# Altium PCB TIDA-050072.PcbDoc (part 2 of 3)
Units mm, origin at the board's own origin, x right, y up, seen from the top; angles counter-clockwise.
Board outline 125.73 x 87.63 mm, 2 copper layers (Top Layer, Bottom Layer), stack 1.575 mm thick; 105 components, 63 nets, 347 pads, 390 vias.
Unrouted connection lines stored in the file: 6.
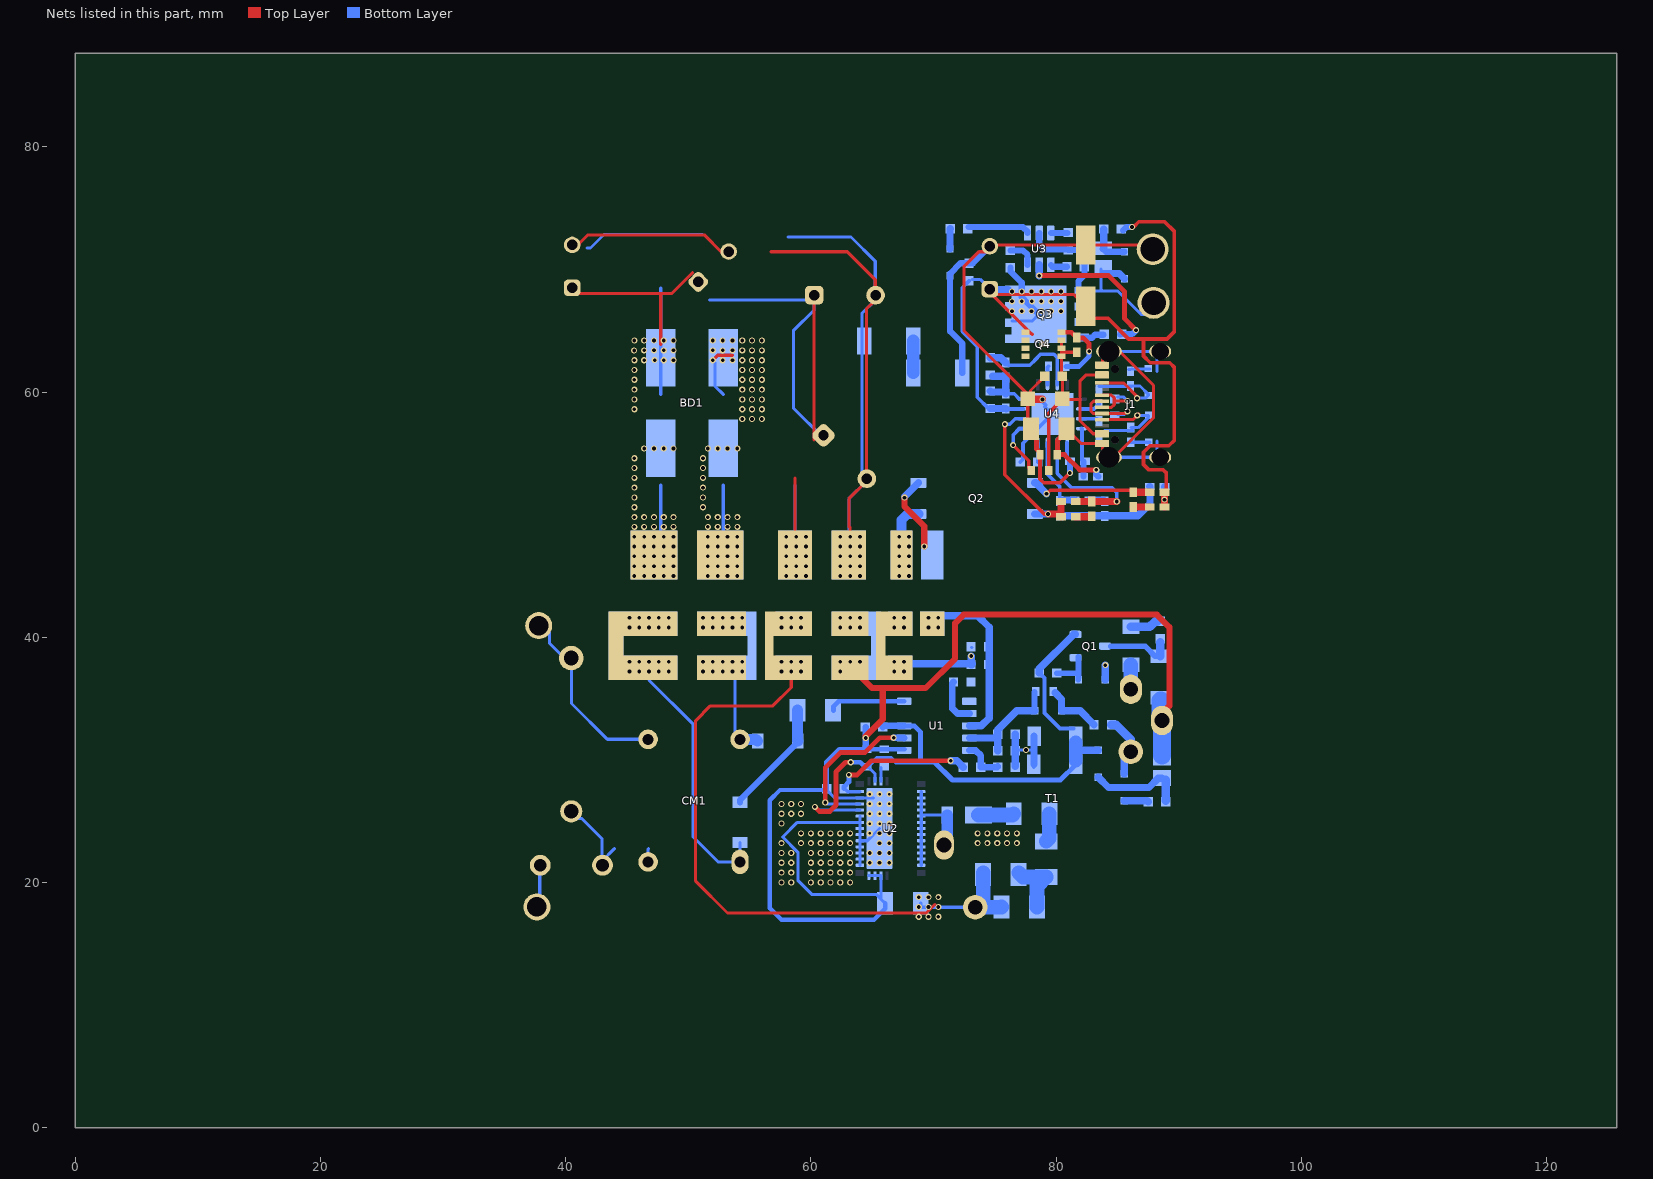
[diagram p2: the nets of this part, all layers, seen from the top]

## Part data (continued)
R8 R9: library part CMP-0018730-2, "RES, 7.5, 5%, 0.25 W, 1206", Manufacturer=Vishay-Dale, Power_W=250mW, Supplier Part Number 1=541-7.5ECT-ND, TempCo="200 ppm/C", Tolerance_%=5%, Value2=0.25W, Value_Code=7R50, ValueDisplayed=7.5
R10 R12: library part CMP-0022892-5, "RES, 1.80 k, 1%, 0.1 W, 0603", Manufacturer=Yageo, Power_W=100mW, Supplier Part Number 1=311-1.80KHRCT-ND, TempCo="100 ppm/C", Tolerance_%=1%, Value2=0.1W, Value_Code=1k80, ValueDisplayed=1.80k
R11: library part CMP-0023032-4, "RES, 330 k, 1%, 0.1 W, 0603", Manufacturer=Yageo, Power_W=100mW, Supplier Part Number 1=311-330KHRCT-ND, TempCo="100 ppm/C", Tolerance_%=1%, Value2=0.1W, Value_Code=330k
R13 R16 R18: library part CMP-0025821-1, "RES, 4.7, 5%, 0.1 W, 0603", Manufacturer=Vishay-Dale, Power_W=100mW, Supplier Part Number 1=541-4.7GCT-ND, TempCo="200 ppm/C", Tolerance_%=5%, Value2=0.1W, Value_Code=4R70, ValueDisplayed=4.7
R14: library part CMP-0023073-5, "RES, 39.0 k, 1%, 0.1 W, 0603", Manufacturer=Yageo, Power_W=100mW, Supplier Part Number 1=311-39.0KHRCT-ND, TempCo="100 ppm/C", Tolerance_%=1%, Value2=0.1W, Value_Code=39k0, ValueDisplayed=39.0k
R15: library part CMP-0025812-1, "RES, 470 k, 5%, 0.1 W, 0603", Manufacturer=Vishay-Dale, Power_W=100mW, Supplier Part Number 1=541-470KGCT-ND, TempCo="200 ppm/C", Tolerance_%=5%, Value2=0.1W, Value_Code=470k
R17: library part CMP-0020631-1, "RES, 12, 5%, 0.125 W, 0805", Manufacturer=Panasonic, Power_W=125mW, Supplier Part Number 1=P12ACT-ND, TempCo="200 ppm/C", Tolerance_%=5%, Value2=0.125W, Value_Code=12R0, ValueDisplayed=12
R19 R21: library part CMP-0025910-5, "RES, 300, 5%, 0.1 W, 0603", Manufacturer=Yageo, Power_W=100mW, Supplier Part Number 1=311-300GRCT-ND, TempCo="100 ppm/C", Tolerance_%=5%, Value2=0.1W, Value_Code=300R, ValueDisplayed=300
R22: library part CMP-0025975-2, "RES, 11.0 k, 1%, 0.063 W, 0402", Manufacturer=Vishay-Dale, Power_W=63mW, Supplier Part Number 1=541-11.0KLCT-ND, TempCo="100 ppm/C", Tolerance_%=1%, Value2=0.063W, Value_Code=11k0, ValueDisplayed=11.0k
R23: library part CMP-0026402-1, "RES, 499, 1%, 0.063 W, 0402", Manufacturer=Vishay-Dale, Power_W=63mW, Supplier Part Number 1=541-499LCT-ND, TempCo="100 ppm/C", Tolerance_%=1%, Value2=0.063W, Value_Code=499R, ValueDisplayed=499
R24 R25: library part CMP-0027003-2, "RES, 47, 5%, 0.063 W, 0402", Manufacturer=Rohm, Power_W=63mW, Supplier Part Number 1=RHM47JCT-ND, TempCo="200 ppm/C", Tolerance_%=5%, Value2=0.063W, Value_Code=47R0, ValueDisplayed=47
R26: library part CMP-0026907-1, "RES, 33 k, 5%, 0.063 W, 0402", Manufacturer=Vishay-Dale, Power_W=63mW, Supplier Part Number 1=541-33KJCT-ND, TempCo="200 ppm/C", Tolerance_%=5%, Value2=0.063W, Value_Code=33k0, ValueDisplayed=33k
R27: library part CMP-0025886-5, "RES, 10 k, 5%, 0.1 W, 0603", Manufacturer=Yageo, Power_W=100mW, Supplier Part Number 1=311-10KGRCT-ND, TempCo="100 ppm/C", Tolerance_%=5%, Value2=0.1W, Value_Code=10k0, ValueDisplayed=10k
R28: library part CMP-0026859-2, "RES, 1.0 M, 5%, 0.063 W, AEC-Q200 Grade 0, 0402", Manufacturer=Vishay-Dale, Power_W=63mW, Supplier Part Number 1=541-1.0MJCT-ND, TempCo="200 ppm/C", Tolerance_%=5%, Value2=0.063W, Value_Code=1M00, ValueDisplayed=1.0M
R29: library part CMP-0022109-1, "RES, 1.00 k, 1%, 0.1 W, 0603", Manufacturer=Vishay-Dale, Power_W=100mW, Supplier Part Number 1=541-1.00KHCT-ND, TempCo="100 ppm/C", Tolerance_%=1%, Value2=0.1W, Value_Code=1k00, ValueDisplayed=1.00k
R30: library part CMP-0078497-1, "RES, 0.005, 1%, 1 W, 1206", Manufacturer=Riedon, Power_W=1W, Supplier Part Number 1=696-1372-1-ND, TempCo="50 ppm/C", Tolerance_%=1%, Value_Code=5L000, ValueDisplayed=0.005
R31: library part CMP-0026951-3, "RES, 5.1 k, 5%, 0.063 W, 0402", Manufacturer=Vishay-Dale, Power_W=63mW, Supplier Part Number 1=541-5.1KJCT-ND, TempCo="200 ppm/C", Tolerance_%=5%, Value2=0.063W, Value_Code=5k10, ValueDisplayed=5.1k
R32: library part CMP-0026938-5, "RES, 4.7 k, 5%, 0.063 W, AEC-Q200 Grade 0, 0402", Manufacturer=Vishay-Dale, Power_W=63mW, Supplier Part Number 1=541-4.7KJCT-ND, TempCo="200 ppm/C", Tolerance_%=5%, Value2=0.063W, Value_Code=4k70, ValueDisplayed=4.7k
R33: library part CMP-0026935-2, "RES, 47 k, 5%, 0.063 W, 0402", Manufacturer=Vishay-Dale, Power_W=63mW, Supplier Part Number 1=541-47KJCT-ND, TempCo="200 ppm/C", Tolerance_%=5%, Value2=0.063W, Value_Code=47k0, ValueDisplayed=47k
R34: library part CMP-0025700-3, "RES, 100, 5%, 0.1 W, 0603", Manufacturer=Vishay-Dale, Power_W=100mW, Supplier Part Number 1=541-100GCT-ND, TempCo="200 ppm/C", Tolerance_%=5%, Value2=0.1W, Value_Code=100R, ValueDisplayed=100
RT1: library part CMP-0002440-2, "Thermistor NTC, 220k ohm, 3%, 0603", Manufacturer=MuRata, Power_W=100mW, Supplier Part Number 1=490-8456-1-ND, Tolerance_%=3%
T1: library part RM8_65W, Alternate Manufacturer=-, Manufacturer="Used in BOM report"
U1: library part CMP-0094882-1, "Converter Offline Flyback Topology 50kHz", Manufacturer=onsemi, Max Power Dissipation=330mW, Max Supply Voltage=28V, Min Supply Voltage=8.5V, Mouser Part Number=863-CP1342AMDCDD1R2G, Nominal Supply Current=0.115-1mA, Operating Temperature Range="-40°C to +125°C", Supplier Part Number 1=NCP1342AMAACD1R2GOSCT-ND, Switching Frequency=25kHz
U2: library part CMP-0096535-2, "650-V GaN FET With Integrated Driver and Current Sense Emulation", Manufacturer="Texas Instruments", Max Supply Voltage=26V, Min Supply Voltage=10V, Operating Temperature Range="-40°C to +175°C"
U3: library part CMP-0086802-1, "FAST TURN-OFF INTELLIGENT RECTIF", Manufacturer="Monolithic Power Systems"
U4: library part CMP-0087009-1, "USB PD/QC4/QC4+ Controller", Manufacturer=Weltrend

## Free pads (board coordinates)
  rect 1.2x5.6 smd: 1(44.1,39.3)
  rect 1.2x5.6 smd far side: 1(44.1,39.3)
  rect 4.6x2 smd: 1(46.8,37.5) 1(46.8,41.1)
  rect 4.6x2 smd far side: 1(46.8,37.5) 1(46.8,41.1)
  rect 3.8x4 smd: 1(47.2,46.7) 1(52.6,46.7)
  rect 3.8x4 smd far side: 1(47.2,46.7) 1(52.6,46.7)
  rect 4x2 smd: 1(52.7,37.5) 1(52.7,41.1)
  rect 4.4x2 smd far side: 1(52.9,37.5) 1(52.9,41.1)
  rect 0.7x5.6 smd far side: 1(55.2,39.3)
  rect 0.7x5.6 smd: 1(56.6,39.3)
  rect 3.4x2 smd: 1(58.4,37.5) 1(58.4,41.1)
  rect 3x2 smd far side: 1(58.6,37.5) 1(58.6,41.1)
  rect 2.8x4 smd: 1(58.7,46.7) 1(63.1,46.7)
  rect 2.8x4 smd far side: 1(58.7,46.7) 1(63.1,46.7)
  rect 3x2 smd: 1(63.2,37.5) 1(63.2,41.1)
  rect 3.4x2 smd far side: 1(63.4,37.5) 1(63.4,41.1)
  rect 0.8x5.6 smd far side: 1(65.3,39.3)
  rect 0.8x5.6 smd: 1(65.7,39.3)
  rect 2.4x2 smd: 1(67.1,37.5) 1(67.1,41.1)
  rect 2x2 smd far side: 1(67.3,37.5) 1(67.3,41.1) 1(69.9,41.1)
  rect 1.8x4 smd: 1(67.4,46.7)
  rect 1.8x4 smd far side: 1(67.4,46.7) 1(69.9,46.7)
  rect 2x2 smd: 1(69.9,41.1)

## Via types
v1: diameter 0.5, hole 0.3, Top Layer to Bottom Layer, 375 vias
v2: diameter 0.5, hole 0.2, Top Layer to Bottom Layer, tented both sides, 13 vias
v3: diameter 0.5, hole 0.3, Top Layer to Bottom Layer, tented both sides, 2 vias

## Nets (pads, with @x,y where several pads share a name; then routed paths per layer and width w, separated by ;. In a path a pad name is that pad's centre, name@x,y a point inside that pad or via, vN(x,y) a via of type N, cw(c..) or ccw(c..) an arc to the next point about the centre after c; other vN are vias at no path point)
AUX_QR: D6.2 R12.2 T1.4 | length 5.1
  Bottom Layer w0.6: D6.2@85.575,28.85 85.575,30.145 T1.4@86.1,30.67
  Bottom Layer w0.7: R12.2@84.518,32.868 84.896,32.868 86.1,31.664 T1.4@86.1,30.67
CC1: C33.1 D13.2 J1.A5 R25.1 | length 9
  Top Layer w0.254: J1.A5@83.791,57.75 86.275,57.75 v1@86.75,58.225
  Bottom Layer w0.254: R25.1@83.5,56.45 83.561,56.45 83.966,56.855 C33.1@86.255,56.855 ; C33.1@86.1,57.1 86.7,57.1 87.55,57.95 D13.2@87.55,58.1 v1(86.625,58.1)
CC2: C34.1 D14.2 J1.B5 R24.1 | length 8.9
  Top Layer w0.254: J1.B5@83.791,60.75 85.5,60.75 v1@86.75,59.5
  Bottom Layer w0.254: R24.1@83.525,60.475 C34.1@86.15,60.475 ; C34.1@86.075,60.5 86.85,60.5 87.525,59.825 D14.2@87.525,59.725 87.3,59.5 v1(86.6,59.5)
CS_QR: R3.1 R6.1 U2.33 | length 12.7
  Top Layer w0.4: v1(63.1,28.775) 63.777,28.775 64.927,29.925 v1(71.4,29.925)
  Bottom Layer w0.254: R3.1@62.711,27.7 62.736,27.675 63.011,27.4 U2.33@64,27.4
  Bottom Layer w0.4: R3.1@62.711,27.65 62.711,27.7 62.711,27.811 63.1,28.2 v1(63.1,28.775)
  Bottom Layer w0.6: v1(71.4,29.925) 71.914,29.925 R6.1@72.439,29.4
DRV_QR: U1.7 U2.31 | length 13.2
  Top Layer w0.4: v1(61.175,26.525) 61.175,29.359 62.4,30.584 64.404,30.584 65.62,31.8 v1(66.75,31.8)
  Bottom Layer w0.254: v1(61.175,26.525) 61.3,26.4 U2.31@64,26.4
  Bottom Layer w0.5: v1(66.75,31.8) 67.59,31.8 U1.7@67.615,31.775 U1.7@67.597,31.757
FLT_QR: U1.1
G: BD1.4 C2.2 C3.2 C4.2 C5.2 C6.2 C6A.2 C7.2 C8.2 C10.2 C11.2 C12.2 C13.2 C14.2 C15.2 CY1.2 D5.2 pad.1@63.1,46.7 pad.1@63.2,37.5 pad.1@63.2,41.1 pad.1@63.4,37.5 pad.1@63.4,41.1 pad.1@65.3,39.3 pad.1@65.7,39.3 pad.1@67.1,37.5 pad.1@67.1,41.1 pad.1@67.3,37.5 pad.1@67.3,41.1 pad.1@67.4,46.7 Q2.4 R3.2 R4.2 R5.2 R10.1 R14.1 T1.6 U1.6 U2.17 U2.18 U2.19 U2.21 U2.22 U2.23 U2.24 U2.25 U2.26 U2.27 U2.28 U2.29 U2.32 U2.39 | length 238.1
  Top Layer w0.254: C6.2@40.525,71.525 41.825,72.825 51.3,72.825 C6A.2@52.75,71.375 ; v1(52,62.6) 52.4,63 53.6,63 ; 56.75,71.45 62.975,71.45 65.25,69.175 65.25,67.5 64.543,66.793 64.543,52.732 63.1,51.289 63.1,49 ; v1(62.4,41.6) 62.9,41.1 pad.1@63.2,41.1 ; v1(62.4,46.6) 62.729,46.6 pad.1@62.8,46.529 ; pad.1@63.1,47.4 62.8,47.1 62.8,46.6 63,46.6 63.071,46.671 pad.1@63.428,46.671 ; pad.1@63.2,37.5 63.2,37.6 63.265,37.665 pad.1@63.6,38 ; v1(63.2,47.4) v1(63.2,48.2) 63.2,49 ; pad.1@67.2,45.4 67.4,45.6 pad.1@67.4,46.7 ; T1.6@88.64,33.21 T1.6@88.64,33.79
  Top Layer w0.5: pad.1@63.2,37.5 63.344,37.5 64.994,35.85 65.861,35.85 ; v1(64.475,31.775) 64.475,31.925 65.861,33.311 65.861,35.85 ; T1.6@88.64,33.79 89.25,34.4 89.25,40.827 88.227,41.85 72.475,41.85 71.763,41.138 71.763,38.263 69.35,35.85 65.861,35.85
  Bottom Layer w0.254: 41.75,71.75 42.028,71.75 43.128,72.85 51.168,72.85 ; 52.85,59.81 52.175,60.485 52.175,62.425 v1(52,62.6) 52.4,63 BD1.4@53.6,63 ; 58.125,72.65 63.275,72.65 65.25,70.675 65.25,67.5 64.175,66.425 64.175,53.1 64.543,52.732 63.1,51.289 63.1,47.4 62.8,47.1 62.8,46.6 63,46.6 63.071,46.671 pad.1@63.428,46.671 ; R3.2@61.289,27.536 61.925,26.9 U2.32@64,26.9 U2.39@65.1,26.9 ; v1(62.4,41.6) 62.9,41.1 pad.1@63.4,41.1 ; v1(62.4,46.6) 62.729,46.6 pad.1@62.8,46.529 ; U2.21@64,21.4 U2.22@64,21.9 U2.23@64,22.4 U2.24@64,22.9 U2.25@64,23.4 ; U2.29@64,25.4 U2.28@64,24.9 ; U2.19@64.725,20.55 U2.18@65.225,20.55 U2.17@65.725,20.55 C8.2@65.725,18.636 ; U2.39@65.6,24.4 64.6,23.4 U2.25@64,23.4 ; C8.2@66.061,18.3 C8.2@65.725,18.636 ; pad.1@67.2,45.4 67.4,45.6 pad.1@67.4,46.7 ; C15.2@73.114,39.162 C15.2@73.128,39.176 ; R10.1@76.674,30.75 76.724,30.8 v1(77.55,30.8) 78.154,30.8 78.204,30.85 ; C13.2@78.177,29.375 C13.2@78.225,29.423 ; U2.25@64,23.4 U2.26@64,23.9 U2.27@64,24.4 U2.28@64,24.9 ; U2.28@64,24.9 58.9,24.9 57.7,23.7 58.937,22.463 58.937,20.162 60.1,19 65.361,19 C8.2@65.725,18.636
  Bottom Layer w0.35: R3.2@61.289,27.536 57.486,27.536 56.65,26.7 56.65,17.9 57.6,16.95 65.15,16.95 66.061,17.861 C8.2@66.061,18.3
  Bottom Layer w0.4: R3.2@61.289,27.536 R3.2@61.289,27.65 61.289,29.839 62.311,30.861 C3.2@64.575,30.861 ; C3.2@64.7,30.861 R4.2@65.975,30.861 U1.6@67.64,30.861
  Bottom Layer w0.5: C3.2@64.475,31 v1(64.475,31.775) C2.2@64.475,32.678
  Bottom Layer w0.6: pad.1@67.6,37.4 68.05,37.85 R14.1@73.15,37.85 ; R14.1@73.075,37.761 R14.1@73.075,37.975 ; R14.1@73.075,38 v1(73.075,38.475) ; R14.1@73.114,37.75 R14.1@73.125,37.761 ; C7.2@76.674,29.45 R10.1@76.674,30.75 C10.2@76.674,32.09 ; C13.2@78.2,29.65 78.204,29.654 78.204,30.85 C14.2@78.204,31.914 ; D5.2@84.025,36.525 v1(84.025,37.725)
  Bottom Layer w0.8: pad.1@67.4,46.7 67.4,49.575 67.875,50.05 Q2.4@68.775,50.05
  Bottom Layer w1.5: T1.6@88.536,33.104 C12.2@88.536,34.819 ; C11.2@88.64,30.386 T1.6@88.64,33.396
  other v1: 57.6,20 58.4,20 60,20 60.8,20 61.6,20 62.4,20 63.2,20 57.6,20.8 58.4,20.8 60,20.8 60.8,20.8 61.6,20.8 62.4,20.8 63.2,20.8 57.6,21.6 58.4,21.6 60,21.6 60.8,21.6 61.6,21.6 62.4,21.6 63.2,21.6 64.8,21.6 65.6,21.6 66.4,21.6 57.6,22.4 58.4,22.4 60,22.4 60.8,22.4 61.6,22.4 62.4,22.4 63.2,22.4 64.8,22.4 65.6,22.4 66.4,22.4 57.6,23.2 59.2,23.2 60,23.2 60.8,23.2 61.6,23.2 62.4,23.2 63.2,23.2 65.6,23.2 66.4,23.2 59.2,24 60,24 60.8,24 61.6,24 62.4,24 63.2,24 57.6,24.8 57.6,25.6 58.4,25.6 59.2,25.6 57.6,26.4 58.4,26.4 59.2,26.4 62.4,37.2 66.8,37.2 67.6,37.2 62.4,38 63.2,38 64,38 66.8,38 67.6,38 62.4,40.8 63.2,40.8 64,40.8 66.8,40.8 67.6,40.8 63.2,41.6 64,41.6 66.8,41.6 67.6,41.6 62.4,45 63.2,45 64,45 67.2,45 68,45 62.4,45.8 63.2,45.8 64,45.8 67.2,45.8 68,45.8 63.2,46.6 64,46.6 67.2,46.6 68,46.6 62.4,47.4 64,47.4 67.2,47.4 68,47.4 62.4,48.2 64,48.2 67.2,48.2 68,48.2 54.4,57.8 55.2,57.8 56,57.8 54.4,58.6 55.2,58.6 56,58.6 54.4,59.4 55.2,59.4 56,59.4 54.4,60.2 55.2,60.2 56,60.2 54.4,61 55.2,61 56,61 54.4,61.8 55.2,61.8 56,61.8 52.8,62.6 53.6,62.6 54.4,62.6 55.2,62.6 56,62.6 52,63.4 52.8,63.4 53.6,63.4 54.4,63.4 55.2,63.4 56,63.4 52,64.2 52.8,64.2 53.6,64.2 54.4,64.2 55.2,64.2 56,64.2
  other v2: 64.8,24 64.8,24.8 65.6,24.8 66.4,24.8 64.8,25.6 65.6,25.6 66.4,25.6 64.8,26.4 65.6,26.4 66.4,26.4 64.8,27.2 65.6,27.2 66.4,27.2
  other v3: 65.6,24 66.4,24
GPD: R27.1 U4.2 | length 1.5
  Bottom Layer w0.3: U4.2@79.3,60.6 79.3,62.011 R27.1@79.389,62.1
Net+_1: +.1 C17.2 D10.2 Q3.1 Q3.2 Q3.3 R17.1 R20.1 U3.2 | length 20.6
  Bottom Layer w0.254: Q3.3@82.1,65.705 Q3.2@82.1,66.975 Q3.1@82.1,68.245 83.674,68.245 83.8,68.245 ; R17.1@83.674,70.017 83.674,69.675 83.674,68.371 83.8,68.245 ; +.1@87.8,66.35 86.925,66.35 85.03,68.245 83.8,68.245
  Bottom Layer w0.5: U3.2@78.625,72.975 78.625,72.05 79.025,71.65 R20.1@80.85,71.65 ; R20.1@81,71.589 81.739,71.589 82.311,71.017 C17.2@82.311,70.225 82.311,69.526 81.825,69.04 Q3.1@81.825,68.273
  Bottom Layer w0.6: 83.864,69.675 85.164,69.675 D10.2@85.589,69.25
NetBD1_1: BD1.1 C4.1 C5.1 C6.1 C6A.1 C8.1 C9.1 pad.1@56.6,39.3 pad.1@58.4,37.5 pad.1@58.4,41.1 pad.1@58.6,37.5 pad.1@58.6,41.1 pad.1@58.7,46.7 R7.2 T1.1 | length 132.6
  Top Layer w0.254: C6.1@40.525,68.025 47.7,68.025 ; 47.75,63.9 47.75,67.975 47.7,68.025 ; 50.35,69.75 48.625,68.025 47.7,68.025 ; pad.1@57.4,41.664 57.964,41.1 pad.1@58.4,41.1 ; 58.7,52.975 58.7,48.2 58.7,47.4 pad.1@58.7,46.7 v1(58.8,46.6) ; pad.1@58.8,37.6 58.5,37.6 pad.1@58.4,37.5 58.4,35.9 56.9,34.4 51.8,34.4 50.6,33.2 50.6,20.1 53.2,17.5 69.414,17.5 70.114,18.2 ; v1(58.8,45.8) v1(58.8,46.6) ; v1(59.6,45) v1(59.6,45.8) v1(58.8,46.6) ; C4.1@60.25,67.5 60.25,56.1 60.418,56.268 C5.1@61.007,56.268
  Bottom Layer w0.254: 47.75,59.81 47.75,63.9 47.75,68.5 ; 51.75,67.5 60.25,67.5 60.25,66.675 58.575,65 58.575,58.7 C5.1@61.007,56.268 ; pad.1@57.4,41.664 57.964,41.1 pad.1@58.6,41.1 ; pad.1@58.6,37.5 58.7,37.6 pad.1@58.8,37.6 ; 58.7,52.4 58.7,48.2 58.7,47.4 pad.1@58.7,46.7 v1(58.8,46.6) ; v1(58.8,45.8) v1(58.8,46.6) ; v1(59.6,45) v1(59.6,45.8) v1(58.8,46.6) ; C8.1@68.961,18.3 68.961,18.089 69.08,17.97 T1.1@73.4,17.97
  Bottom Layer w1.2: C9.1@74.05,20.8 74.05,18.62 T1.1@73.4,17.97 75.52,17.97 R7.2@75.55,18
  other v1: 68.8,17.2 69.6,17.2 70.4,17.2 68.8,18 69.6,18 70.4,18 68.8,18.8 69.6,18.8 70.4,18.8 57.6,37.2 58.4,37.2 59.2,37.2 57.6,38 58.4,38 59.2,38 57.6,40.8 58.4,40.8 59.2,40.8 57.6,41.6 58.4,41.6 59.2,41.6 58,45 58.8,45 58,45.8 58,46.6 59.6,46.6 58,47.4 58.8,47.4 59.6,47.4 58,48.2 58.8,48.2 59.6,48.2 45.6,58.6 45.6,59.4 45.6,60.2 45.6,61 45.6,61.8 45.6,62.6 46.4,62.6 47.257,62.602 48,62.6 48.8,62.6 45.581,63.387 46.4,63.4 47.2,63.4 48,63.4 48.8,63.4 45.6,64.2 46.4,64.2 47.2,64.2 48,64.2 48.8,64.2
NetBD1_2: BD1.2 CM1.4 D2.2 pad.1@44.1,39.3 pad.1@46.8,37.5 pad.1@46.8,41.1 pad.1@47.2,46.7 | length 34.5
  Top Layer w0.254: v1(48.4,40.8) 48.1,41.1 pad.1@46.8,41.1 47.3,41.6 v1(48.4,41.6)
  Bottom Layer w0.254: pad.1@46.8,37.5 46.8,36.5 50.4,32.9 50.4,23.7 52.425,21.675 CM1.4@54.225,21.675 D2.2@54.225,23.262 ; pad.1@47.2,46.7 47.75,47.25 47.75,52.41 ; v1(48.4,40.8) 48.1,41.1 pad.1@46.8,41.1 47.3,41.6 v1(48.4,41.6)
  other v1: 45.2,37.2 46,37.2 46.8,37.2 47.6,37.2 48.4,37.2 45.2,38 46,38 46.8,38 47.6,38 48.4,38 45.2,40.8 46,40.8 46.8,40.8 47.6,40.8 45.2,41.6 46,41.6 46.8,41.6 47.6,41.6 45.6,45 46.4,45 47.2,45 48,45 48.8,45 45.6,45.8 46.4,45.8 47.2,45.8 48,45.8 48.8,45.8 45.6,46.6 46.4,46.6 47.2,46.6 48,46.6 48.8,46.6 45.6,47.4 46.4,47.4 47.187,47.4 48.01,47.4 48.8,47.4 45.6,48.2 46.4,48.2 47.2,48.2 48,48.2 48.8,48.2 45.6,49 46.4,49 47.2,49 48,49 48.8,49 45.6,49.8 46.4,49.8 47.2,49.8 48,49.8 48.8,49.8 45.6,50.6 45.6,51.4 45.6,52.2 45.6,53 45.6,53.8 45.6,54.6 46.4,55.4 47.2,55.4 48,55.4 48.8,55.4
NetBD1_3: BD1.3 CM1.3 D1.2 pad.1@52.6,46.7 pad.1@52.7,37.5 pad.1@52.7,41.1 pad.1@52.9,37.5 pad.1@52.9,41.1 pad.1@55.2,39.3 | length 30.1
  Top Layer w0.254: pad.1@51.2,48.2 51.2,48.1 pad.1@51.95,47.35 ; pad.1@52,47.4 52,47.3 52.12,47.18 pad.1@52.4,46.9 ; v1(52.4,48.2) pad.1@52.4,46.9 ; pad.1@52.8,48.2 52.6,48 pad.1@52.6,47.2 ; pad.1@53.6,48.2 52.8,47.4 pad.1@52.6,47.2 ; v1(54,48.2) 52.6,46.8 pad.1@52.6,46.7 ; pad.1@52.4,46.9 pad.1@52.6,46.7 ; pad.1@52.6,46.7 pad.1@52.6,47.2
  Bottom Layer w0.254: pad.1@51.2,48.2 51.2,48.1 pad.1@51.95,47.35 ; pad.1@52,47.4 52,47.3 52.12,47.18 pad.1@52.4,46.9 ; v1(52.4,48.2) pad.1@52.4,46.9 ; pad.1@52.6,47.2 52.6,48.45 52.85,48.7 52.85,52.41 ; pad.1@52.8,47.4 52.75,47.4 52.6,47.25 pad.1@52.6,46.7 ; pad.1@52.8,48.2 52.8,47.5 pad.1@52.85,47.45 ; pad.1@52.85,46.95 pad.1@52.85,47.45 ; pad.1@53.6,48.2 pad.1@52.85,47.45 ; pad.1@53.8,37.662 53.8,32.1 CM1.3@54.225,31.675 ; v1(54,48.2) 52.8,47 52.6,46.8 pad.1@52.6,46.7 ; pad.1@52.4,46.9 pad.1@52.6,46.7
  Bottom Layer w0.9: CM1.3@54.225,31.675 55.537,31.675 D1.2@55.662,31.55
  other v1: 51.2,37.2 52,37.2 52.8,37.2 53.6,37.2 54.4,37.2 51.2,38 52,38 52.8,38 53.6,38 54.4,38 51.2,40.8 52,40.8 52.8,40.8 53.6,40.8 54.4,40.8 51.2,41.6 52,41.6 52.8,41.6 53.6,41.6 54.4,41.6 51.6,45 52.4,45 53.2,45 54,45 51.6,45.8 52.4,45.8 53.2,45.8 54,45.8 51.6,46.6 52.4,46.6 53.2,46.6 54,46.6 51.6,47.4 52.4,47.4 53.2,47.4 54,47.4 51.6,48.2 53.2,48.2 51.6,49 52.4,49 53.2,49 54,49 51.6,49.8 52.4,49.8 53.2,49.8 54,49.8 51.2,50.6 51.2,51.4 51.2,52.2 51.2,53 51.2,53.8 51.2,54.6 51.6,55.4 52.4,55.4 53.2,55.4 54,55.4
NetC7_1: C7.1 R6.2 U1.5 | length 3.5
  Bottom Layer w0.55: U1.5@72.935,30.775 73.428,30.775 73.861,30.341 R6.2@73.861,29.4 75.201,29.4 C7.1@75.251,29.45
NetC9_2: C9.2 R7.1 R8.2 | length 5.2
  Bottom Layer w1.2: C9.2@76.95,20.8 77.3,20.45 R8.2@79.2,20.45 78.45,19.7 R7.1@78.45,18
NetC10_1: C10.1 D4.1 R10.2 R11.1 U1.4 | length 9.3
  Bottom Layer w0.5: D4.1@78.25,34 R11.1@78.25,35.536
  Bottom Layer w0.55: U1.4@72.935,31.775 74.936,31.775 C10.1@75.251,32.09
  Bottom Layer w0.6: R10.2@75.251,30.75 C10.1@75.251,32.09 75.251,32.458 76.793,34 D4.1@78.25,34
NetC11_1: C11.1 D7.2 R13.1 | length 7.5
  Bottom Layer w0.6: D7.2@83.45,28.578 84.28,27.748 87.586,27.748 88.339,28.5 C11.1@88.64,28.5
  Bottom Layer w0.7: R13.1@88.95,26.675 C11.1@88.95,28.37
NetC12_1: C12.1 Q1.3 R16.1 | length 5.5
  Bottom Layer w0.45: Q1.3@84.45,39.251 87.286,39.251 88.088,38.45 C12.1@88.515,38.45
  Bottom Layer w0.7: C12.1@88.515,38.45 R16.1@88.515,39.596
NetC15_1: C15.1 pad.1@69.9,41.1 pad.1@69.9,46.7 Q2.6 R14.2 U1.3 | length 21.1
  Top Layer w0.5: v1@67.64,51.394 v1(67.64,51.385) 67.64,50.66 69.25,49.05 v1(69.25,47.4)
  Bottom Layer w0.6: v1(67.64,51.385) 67.64,51.455 Q2.6@68.775,52.59 ; pad.1@69.9,41.1 69.8,41.1 70.44,41.74 73.626,41.74 74.536,40.83 74.536,37.775 74.536,33.4 73.911,32.775 U1.3@72.935,32.775
  other v1: 69.6,40.8 70.4,40.8 69.6,41.6 70.4,41.6
NetC16_2: C16.2 D10.1 R17.2 | length 3.5
  Bottom Layer w0.5: R17.2@83.864,71.675 84.089,71.45 D10.1@85.589,71.45
  Bottom Layer w0.6: R17.2@83.864,71.675 83.889,71.7 C16.2@83.889,73.3
NetC17_1: C17.1 U3.4 | length 1.4
  Bottom Layer w0.5: U3.4@79.575,70.375 79.725,70.225 C17.1@80.889,70.225
NetC21_1: C21.1 C24.1 U4.3 | length 8.4
  Bottom Layer w0.3: C24.1@75.9,62.4 76.113,62.187 77.859,62.187 78.275,62.604 78.275,62.623 78.727,63.075 79.822,63.075 80.1,62.797 U4.3@80.1,60.6
  Bottom Layer w0.6: C21.1@74.636,62.811 75.489,62.811 C24.1@75.9,62.4
NetC22_2: C22.2 R23.2 | length 1.3
  Top Layer w0.6: R23.2@86.3,50.625 C22.2@87.65,50.625
NetC28_2: C28.2 R31.1 U4.8 | length 4.1
  Bottom Layer w0.254: C28.2@82.288,54.288 C28.2@82.353,54.222
  Bottom Layer w0.3: U4.8@82.077,57.023 82.117,56.983 82.117,54.458 C28.2@82.225,54.35
  Bottom Layer w0.5: C28.2@82.225,54.35 82.25,54.325 R31.1@82.25,53.1
NetC29_1: C29.1 R32.1 | length 1.3
  Top Layer w0.254: C29.1@82.865,49.84 C29.1@82.9,49.875
  Top Layer w0.6: R32.1@81.6,49.84 C29.1@82.865,49.84
NetC29_2: C29.2 C31.2 U4.10 | length 12.1
  Top Layer w0.6: C31.2@81.6,51.075 C29.2@82.9,51.075 v1(84.95,51.075)
  Bottom Layer w0.3: U4.10@80.1,55.846 80.1,53.364 81.289,52.175 84.575,52.175 84.95,51.8 v1(84.95,51.075)
NetC30_1: C30.1 R33.1 | length 1.3
  Bottom Layer w0.6: C30.1@82.725,51.2 83.875,51.2 R33.1@83.975,51.1
NetC30_2: C30.2 C32.2 U4.11 | length 6.4
  Bottom Layer w0.3: U4.11@79.3,55.846 79.3,53.292 80.3,52.292 C32.2@80.3,51.104
  Bottom Layer w0.6: C32.2@80.3,51.104 80.396,51.2 C30.2@81.525,51.2
NetCM1_1: CM1.1 CX1.1 F1.1 | length 7.5
  Bottom Layer w0.254: CX1.1@40.475,25.2 41.327,25.2 42.965,23.562 42.965,21.75 43.965,22.75 ; CM1.1@46.725,21.675 46.725,22.725 46.75,22.75
NetCM1_2: CM1.2 CX1.2 N1.1 | length 14
  Bottom Layer w0.254: N1.1@38.675,40.4 38.675,39.5 40.475,37.7 40.475,34.6 43.4,31.675 CM1.2@46.725,31.675
NetCY1_1: CY1.1 CY2.2 | length 2.6
  Bottom Layer w1: CY2.2@68.35,61.55 CY1.1@68.35,64.175
NetD1_1: D1.1 D2.1 R2.1 | length 9.5
  Bottom Layer w0.5: D2.1@54.225,26.537 54.225,26.725 58.937,31.438 D1.1@58.937,31.55
  Bottom Layer w0.9: R2.1@58.918,34.05 58.918,31.569 D1.1@58.937,31.55
NetD3_1: D3.1 R9.2 | length 3.6
  Bottom Layer w0.254: D3.1@73.575,25.725 73.35,25.5 D3.1@73.675,25.5
  Bottom Layer w1.2: D3.1@73.675,25.5 76.45,25.5 R9.2@76.55,25.6
  other v1: 73.6,23.2 74.4,23.2 75.2,23.2 76,23.2 76.8,23.2 73.6,24 74.4,24 75.2,24 76,24 76.8,24
NetD3_2: D3.2 T1.11 U2.2 U2.3 U2.4 U2.5 U2.6 U2.7 U2.8 U2.9 U2.10 U2.11 U2.12 U2.13 U2.14 | length 10.5
  Bottom Layer w0.254: U2.14@69,21.4 U2.13@69,21.9 U2.12@69,22.4 U2.11@69,22.9 U2.10@69,23.4 U2.9@69,23.9 U2.8@69,24.4 U2.7@69,24.9 U2.6@69,25.4 ; U2.2@69,27.4 U2.3@69,26.9 U2.4@69,26.4 U2.5@69,25.9 U2.6@69,25.4 ; T1.11@70.8,23.11 T1.11@70.86,23.05 ; D3.2@70.8,25.5 69.1,25.5 U2.6@69,25.4
  Bottom Layer w0.9: T1.11@70.86,23.05 71.125,23.315 D3.2@71.125,25.5
NetD4_2: D4.2 R11.2 R12.1 | length 4.8
  Bottom Layer w0.6: R11.2@79.925,35.477 80.45,34.952 D4.2@80.45,34 ; D4.2@80.481,34 81.964,34 R12.1@83.096,32.868
NetD5_1: D5.1 Q1.1 R15.2 | length 3.4
  Bottom Layer w0.45: R15.2@80.061,37.079 81.751,37.079 81.825,37.153 ; Q1.1@81.811,38.403 Q1.1@81.836,38.378
  Bottom Layer w0.5: D5.1@81.825,36.718 81.825,37.153 Q1.1@81.825,38.25
NetD6_1: D6.1 R13.2 | length 2
  Bottom Layer w0.6: D6.1@85.575,26.65 87.439,26.65 R13.2@87.514,26.575
NetD8_1: D8.1 R16.2 | length 2.3
  Bottom Layer w0.7: D8.1@86.1,40.85 87.65,40.85 88.083,41.283 R16.2@88.25,41.283
NetD8_2: D8.2 T1.7 | length 2
  Bottom Layer w1.2: T1.7@86.1,35.75 D8.2@86.1,37.75
NetD11_1: D11.1 R21.2 | length 1.7
  Bottom Layer w0.6: D11.1@71.35,71.675 71.35,73.311 R21.2@71.364,73.325
NetF1_2: F1.2 L1.1 | length 3.7
  Bottom Layer w0.254: L1.1@37.55,18.2 37.885,18.535 F1.2@37.885,21.75
NetJ1_A6: J1.A6 J1.B6 R34.1 | length 4.7
  Top Layer w0.254: J1.A6@83.791,58.75 84.525,58.75 84.75,58.975 84.75,59.225 ; J1.B6@83.791,59.75 84.525,59.75 84.75,59.525 84.75,59.225 ; v1(85.825,59.275) 84.8,59.275 84.75,59.225
  Bottom Layer w0.254: R34.1@85.025,59.611 85.489,59.611 v1(85.825,59.275)
NetJ1_A7: J1.A7 J1.B7 R34.2 | length 5.7
  Top Layer w0.254: J1.A7@83.791,59.25 83.05,59.25 82.85,59.05 82.85,58.425 83.025,58.25 83.791,58.25 85.65,58.25 v1(85.825,58.425)
  Bottom Layer w0.254: R34.2@85.025,58.189 85.589,58.189 v1(85.825,58.425)
NetQ3_4: Q3.4 R18.2 | length 1.9
  Bottom Layer w0.254: R18.2@83.864,64.675 R18.2@83.889,64.7
  Bottom Layer w0.5: Q3.4@82.1,64.435 82.935,64.435 83.175,64.675 R18.2@83.864,64.675
NetQ4_4: Q4.4 R27.2 R28.1 | length 5.9
  Top Layer w0.4: Q4.4@80.445,64.875 81.25,64.875 R28.1@81.675,64.45 81.7,64.425 82.221,64.425 82.7,63.946 v1(82.7,63.32)
  Bottom Layer w0.4: R27.2@80.811,62.1 81.878,62.1 82.7,62.922 v1(82.7,63.32)
NetR2_2: R2.2 U1.10 | length 6.3
  Bottom Layer w0.4: R2.2@61.85,34 61.85,34.361 62.264,34.775 U1.10@67.615,34.775
NetR4_1: R4.1 U2.37 | length 1.1
  Bottom Layer w0.254: U2.37@65.725,28.25 R4.1@65.725,29.35
NetR5_1: R5.1 U1.2 | length 3.8
  Bottom Layer w0.55: R5.1@71.639,36.35 71.542,36.253 71.542,34.191 71.958,33.775 U1.2@72.935,33.775
NetR8_1: R8.1 R9.1 | length 2.4
  Bottom Layer w1.2: R8.1@79.2,23.35 79.45,23.6 R9.1@79.45,25.6
NetR18_1: R18.1 U3.5 | length 13.3
  Top Layer w0.4: v1(78.625,69.5) 84.286,69.5 85.592,68.194 85.592,65.983 v1(86.525,65.05)
  Bottom Layer w0.5: R18.1@85.236,64.7 R18.1@85.286,64.75 ; R18.1@85.361,64.725 86.2,64.725 v1(86.525,65.05)
  Bottom Layer w0.6: v1(78.625,69.5) U3.5@78.625,70.375
NetR19_1: R19.1 U3.6 | length 2.4
  Bottom Layer w0.5: R19.1@76.275,71.561 77.301,71.561 77.675,71.187 U3.6@77.675,70.375
NetR20_2: R20.2 U3.3 | length 1.4
  Bottom Layer w0.254: R20.2@80.947,72.975 R20.2@81,72.922
  Bottom Layer w0.5: U3.3@79.575,72.975 R20.2@80.947,72.975
NetR21_1: R21.1 U3.1 | length 5.1
  Bottom Layer w0.5: R21.1@72.863,73.46 77.301,73.46 77.675,73.085 U3.1@77.675,72.975
NetR24_2: R24.2 U4.6 | length 1.6
  Bottom Layer w0.3: U4.6@82.077,58.623 83.098,58.623 R24.2@83.5,59.025
NetR25_2: R25.2 U4.7 | length 1.5
  Bottom Layer w0.254: R25.2@83.375,57.775 R25.2@83.5,57.65
  Bottom Layer w0.3: U4.7@82.077,57.823 83.327,57.823 R25.2@83.375,57.775
NetR29_1: R29.1 U4.13 | length 4.6
  Top Layer w0.3: v1(76.5,55.668) 77.768,54.399 77.768,53.82 R29.1@77.989,53.6
  Bottom Layer w0.3: v1(76.5,55.668) 76.5,56.503 77.02,57.023 U4.13@77.323,57.023
NetRT1_1: RT1.1 U4.12 | length 1.6
  Bottom Layer w0.3: U4.12@78.5,55.846 78.5,54.311 RT1.1@78.511,54.3
RTN: C27.1 C33.2 C34.2 D13.1 D14.1 J1.1 J1.2 J1.3 J1.4 J1.A1-B12 J1.A12-B1 R30.2 R31.2 | length 40.1
  Top Layer w0.254: R30.2@80.85,57 82.05,55.8 J1.A1-B12@83.75,55.8 ; J1.A1-B12@83.791,55.8 83.791,55.245 84.356,54.68 84.73,54.68 87.95,57.9 87.95,60.55 85.18,63.32 J1.2@84.356,63.32 ; J1.A12-B1@83.791,62.2 83.791,62.755 J1.2@84.356,63.32 ; J1.2@84.315,63.32 J1.2@84.356,63.32 ; J1.3@88.495,54.68 J1.3@88.536,54.68 ; J1.4@88.495,63.32 J1.4@88.536,63.32
  Top Layer w0.4: R30.2@80.85,57 80.85,56.791 80.111,56.052 C27.1@80.111,54.9 80.675,54.9 81.925,53.65 v1(83.275,53.65)
  Bottom Layer w0.254: J1.1@84.356,54.68 J1.3@88.495,54.68 88.536,54.68 88.25,54.966 88.25,56 ; J1.2@84.356,63.32 J1.4@88.495,63.32 88.536,63.32 88.25,63.034 88.25,61.7 ; C33.2@85.9,55.902 C33.2@86.05,55.902 ; C34.2@85.925,61.837 C34.2@86.075,61.837 ; C33.2@86.15,55.902 D13.1@87.65,55.902 ; C34.2@86.15,61.87 D14.1@87.65,61.87
  Bottom Layer w0.5: v1(83.275,53.65) 83.275,53.275 R31.2@83.45,53.1
SGND: -.1 C18.2 C19.2 C20.2 C21.2 C23.2 C24.2 C25.2 C26.2 C27.2 C28.1 CY2.1 D11.2 D12.2 R30.1 RT1.2 U4.9 U4.16 U4.17 | length 70.3
  Top Layer w0.254: D12.2@77.689,59.4 77.689,57.261 R30.1@77.95,57 ; C27.2@78.678,55 78.689,54.989 C27.2@78.697,54.981 ; C26.2@79.089,61.3 77.915,60.126 77.915,59.925 77.8,59.81 77.69,59.81 72.475,65.025 72.475,70.225 73.7,71.45 74.6,71.45 75.15,72 C19.2@82.425,72 87.5,72 -.1@87.8,71.7
  Top Layer w0.3: C27.2@78.689,54.9 78.689,52.911 79,52.6 80.33,52.6 v1(81.124,53.394)
  Top Layer w0.4: R30.1@77.95,57 77.95,56.725 78.412,56.262 78.412,55.337 78.689,55.061 78.689,54.989 C27.2@78.689,54.9
  Top Layer w0.6: D12.2@77.689,59.4 v1(78.9,59.4)
  Bottom Layer w0.254: U4.17@79.043,58.829 U4.17@79.675,58.198 ; C28.1@81.124,54.324 C28.1@81.15,54.35
  Bottom Layer w0.3: C23.2@75.9,59.86 76.59,59.86 77.027,59.423 U4.16@77.323,59.423 78.691,59.423 U4.17@79.164,58.95 ; RT1.2@77.089,54.3 77.307,54.519 77.307,55.83 79.675,58.198 U4.17@79.7,58.223 ; U4.9@80.9,55.846 80.9,54.6 C28.1@81.15,54.35
  Bottom Layer w0.5: D11.2@71.35,69.475 71.35,69.669 72.192,70.511 C20.2@72.9,70.511 73.211,70.511 C18.2@74.6,71.9 ; D11.2@71.363,69.306 71.363,64.954 72.35,63.967 CY2.1@72.35,61.55 ; v1(81.124,53.394) C28.1@81.124,54.324
  Bottom Layer w0.6: C25.2@74.636,60.086 74.713,60.01 75.75,60.01 C23.2@75.9,59.86 75.897,59.863 75.897,61.197 C24.2@75.9,61.2 ; C21.2@74.825,61.3 C24.2@75.9,61.3
VBUS: C26.1 D12.1 J1.A4-B9 J1.A9-B4 Q4.1 Q4.2 Q4.3 R28.2 R29.2 | length 21.4
  Top Layer w0.254: R29.2@79.392,53.619 R29.2@79.411,53.6 ; Q4.3@80.445,64.225 Q4.2@80.445,63.575 80.445,63.275 ; R28.2@81.675,63.25 80.47,63.25 80.445,63.275 ; J1.A4-B9@83.791,56.6 83.025,56.6 81.94,57.685 81.94,59.475 ; J1.A9-B4@83.791,61.4 82.45,61.4 81.94,60.89 81.94,59.475 ; 80.445,63.275 Q4.1@80.445,62.925 80.445,61.266 80.511,61.2 80.511,59.422 80.489,59.4 81.865,59.4 81.94,59.475
  Top Layer w0.3: R29.2@79.392,53.619 79.392,58.277 80.489,59.374 D12.1@80.489,59.4
VCC_QR: C2.1 C3.1 C13.1 C14.1 D7.1 Q1.2 R15.1 U1.8 U2.30 U2.36 | length 51.4
  Top Layer w0.4: v1(60.325,26.16) 60.685,25.8 61.55,25.8 62.05,26.3 62.05,29.025 62.825,29.8 v1(63.25,29.8)
  Bottom Layer w0.254: v1(60.325,26.16) 60.585,25.9 U2.30@64,25.9 ; C3.1@64.7,29.4 65.225,28.875 U2.36@65.225,28.25 ; U1.8@67.615,32.775 U1.8@67.64,32.75
  Bottom Layer w0.3: C3.1@64.7,29.4 64.7,29.475 65.375,30.15 66.55,30.15 66.925,29.775 68.975,29.775 ; R15.1@78.653,37.077 79.053,36.677 79.053,33.82 80.323,32.55 C14.1@81.45,32.55
  Bottom Layer w0.4: v1(63.25,29.8) 64.03,29.8 64.392,29.439 C3.1@64.575,29.439 ; U1.8@67.6,32.75 67.64,32.75 68.462,32.75 68.95,32.262 68.95,29.811 70.089,29.811 71.55,28.35 80.35,28.35 81.6,29.6 C13.1@81.6,29.65
  Bottom Layer w0.55: C2.1@65.861,32.675 65.961,32.775 U1.8@67.615,32.775
  Bottom Layer w0.6: R15.1@78.639,37.079 78.639,37.423 81.445,40.229 Q1.2@81.586,40.229 ; 81.781,30.778 D7.1@83.45,30.778
  Bottom Layer w1.1: C13.1@81.6,29.912 C14.1@81.6,31.45
Vfb_a: Q2.1 R22.1 R23.1 | length 10.1
  Top Layer w0.254: R23.1@86.125,52 R23.1@86.3,51.825
  Top Layer w0.3: v1(79.225,51.7) 79.525,52 R23.1@86.125,52
  Top Layer w0.6: R23.1@86.3,51.825 R22.1@87.65,51.825
  Bottom Layer w0.254: Q2.1@78.66,52.59 Q2.1@78.8,52.45
  Bottom Layer w0.6: Q2.1@78.275,52.59 78.335,52.59 v1(79.225,51.7)
Vfb_c: C31.1 C32.1 Q2.3 R26.1 R32.2 R33.2 U4.14 | length 24.1
  Top Layer w0.3: v1(75.825,57.375) 75.825,53.264 79.039,50.05 v1(79.35,50.05)
  Top Layer w0.6: v1(79.35,50.05) 80.19,50.05 R32.2@80.4,49.84 C31.1@80.4,51.075
  Bottom Layer w0.3: v1(75.825,57.375) 76.225,57.375 76.673,57.823 U4.14@77.323,57.823
  Bottom Layer w0.5: v1(79.35,50.05) C32.1@80.154,50.05
  Bottom Layer w0.6: Q2.3@78.275,50.05 v1(79.35,50.05) ; C32.1@80.3,49.904 80.304,49.9 R33.2@83.975,49.9 86.662,49.9 87.662,50.9 87.662,52.288 R26.1@87.65,52.3
Vo: C16.1 C18.1 C19.1 C20.1 C22.1 C23.1 C25.1 Q3.5 Q3.6 Q3.7 Q3.8 Q3.9 Q4.5 Q4.6 Q4.7 Q4.8 Q4.9 R19.2 R22.2 R26.2 U4.15 | length 79.8
  Top Layer w0.254: C18.1@74.6,67.95 C18.1@74.782,67.95 ; 78.091,64.684 78.025,64.75 77.982,64.75 77.741,64.991 C18.1@74.782,67.95 ; C19.1@82.9,67 C19.1@82.425,67 81.475,67.95 C18.1@74.782,67.95
  Top Layer w0.3: C19.1@82.551,66.013 84.236,66.013 85.917,64.331 87.139,64.331 ; v1(86.2,73.46) 86.31,73.46 86.75,73.9 88.853,73.9 89.653,73.1 89.653,64.935 89.049,64.331 87.139,64.331 ; 87.139,64.334 87.139,64.331 ; R22.2@88.85,51.825 89,51.975 89,53.394 88.744,53.65 87.583,53.65 87.139,54.094 87.139,55.096 87.661,55.619 89.199,55.619 89.653,56.072 89.653,62.003 89.265,62.391 87.691,62.391 87.139,62.943 87.139,64.331
  Top Layer w0.6: C22.1@88.85,50.625 v1(88.85,51.225) R22.2@88.85,51.825
  Bottom Layer w0.254: C20.1@73.136,69.189 73.811,69.189 C18.1@74.6,68.4 ; C18.1@74.375,68.175 C18.1@74.6,67.95 ; Q3.9@76.4,65.8 78.06,65.8 Q3.9@78.6,66.34
  Bottom Layer w0.3: C20.1@72.9,69.089 72.9,69.05 72.35,68.5 72.35,64.95 73.575,63.725 73.575,59.584 74.495,58.664 C25.1@74.636,58.664 ; C23.1@75.937,58.623 U4.15@77.323,58.623
  Bottom Layer w0.5: R19.2@76.275,70.139 76.275,69.854 77.197,68.932 77.197,67.743 77.37,67.57 78.17,66.77 Q3.9@78.6,66.34 ; C16.1@85.45,73.175 85.735,73.46 v1(86.2,73.46)
  Bottom Layer w0.6: C18.1@74.6,68.4 74.66,68.34 Q3.8@76.1,68.34 ; C25.1@74.636,58.664 75.896,58.664 C23.1@75.9,58.66 C23.1@75.937,58.623 ; v1(88.85,51.225) R26.2@88.85,52.3
  other v1: 76.4,66.6 77.2,66.6 78,66.6 78.8,66.6 79.6,66.6 80.4,66.6 78.024,67.395 76.4,67.4 77.2,67.4 78.8,67.4 79.6,67.4 80.4,67.4 76.4,68.2 77.2,68.2 78,68.2 78.8,68.2 79.6,68.2 80.4,68.2
pads on no net: J1. J1.A8 J1.B8 T1.2 T1.3 T1.5 T1.8 T1.9 T1.10 T1.12 U2.1 U2.15 U2.16 U2.20 U2.34 U2.35 U2.38 U4.1 U4.4 U4.5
